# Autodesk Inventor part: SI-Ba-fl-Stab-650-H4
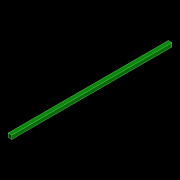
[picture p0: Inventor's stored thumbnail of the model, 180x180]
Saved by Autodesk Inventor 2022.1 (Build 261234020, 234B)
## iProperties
Part Number: SI-Ba-fl-Stab-650-H4
Material: Allgemein
Document SubType Name: Modellieren
Designer: joachim
Appearance: Vorgabe
Author: joachim
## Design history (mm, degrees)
sketch "Skizze1"
  geometry: L1 (0, 0)-(15, 0); L2 (15, 0)-(15, 15); L3 (15, 15)-(0, 15); L4 (0, 15)-(0, 0)
  constraints: 8 end point, 2 parallel, 1 horizontal, 1 perpendicular
  dimensions: "d0" = 15 distance of L3.end L2.end; "d1" = 15 distance of L2.end L1.end
extrude "Extrusion1" new body sketch "Skizze1" distance "d2" = 650; taper "d3" = 0 deg
node "Volumenkörper1"
node "Volumenkörper"
node "Flächenkörper"
